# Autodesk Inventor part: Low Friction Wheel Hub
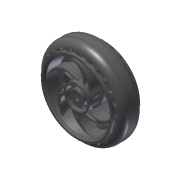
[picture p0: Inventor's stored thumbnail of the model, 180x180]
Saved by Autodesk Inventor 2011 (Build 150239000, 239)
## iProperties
Created: 2010-06
Part Number: Low Friction Wheel Hub
Document SubType Name: Modeling
Designer: kurdi
Density: 1 g/cm^3
Author: kurdi
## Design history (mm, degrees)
sketch "Sketch1"
  geometry: C1 r 4.839 at (0, 0); 1 further point
  constraints: 1 centre point, 1 coincident
  dimensions: "d0" = 9.6774 diameter of C1
extrude "Extrusion1" new body sketch "Sketch1" stored distance "d1" = 19.05; taper "d2" = 0 deg
sketch "Sketch2"
  geometry: C1 r 7.264 at (0, 0); 1 further point
  constraints: 1 centre point, 1 coincident
  dimensions: "d3" = 14.5288 diameter of C1
extrude "Extrusion2" join sketch "Sketch2" stored distance "d4" = 2.0066; taper "d5" = 0 deg
sketch "Sketch3"
  geometry: C1 r 8.585 at (0, 0); C2 r 7.264 at (0, 0) reference; 1 further point
  constraints: 1 centre point, 1 coincident
  dimensions: "d6" = 17.1704 diameter of C1
extrude "Extrusion3" join sketch "Sketch3" stored distance "d7" = 19.05; taper "d8" = 0 deg
sketch "Sketch5"
  geometry: A1 r 22.377 centre (0, 0) between (-12.105, 18.82) and (-12.53, 18.54); A2 r 13.716 centre (-6.985, 6.096) between (6.711, 5.354) and (-12.105, 18.82); A3 r 9.652 centre (-7.874, 9.144) between (1.75, 8.405) and (-4.634, 18.236); A4 r 13.208 centre (-9.068, 5.794) between (-4.634, 18.236) and (-12.53, 18.54); A5 r 12.446 centre (-6.985, 6.096) between (5.449, 6.634) and (2.875, 13.691); A6 r 10.922 centre (-7.874, 9.144) between (2.993, 8.047) and (2.221, 13.313); A7 r 0.381 centre (2.573, 13.458) between (2.875, 13.691) and (2.221, 13.313); A8 r 8.585 centre (0, 0) between (2.993, 8.047) and (5.449, 6.634) reference; A9 r 8.585 centre (0, 0) between (2.993, 8.047) and (1.75, 8.405); A10 r 8.585 centre (0, 0) between (6.711, 5.354) and (5.449, 6.634)
  constraints: 20 point on circle, 9 centre point, 3 concentric, 3 tangent
  dimensions: "d29" = 0.381 radius of A7; "d30" = 22.3774 radius of A1; "d31" = 13.716 radius of A2; "d32" = 9.652 radius of A3; "d33" = 13.208 radius of A4; "d44" = 9.83102 vertical distance of A3.start A3.end; "d45" = 1.27 radial gap between concentric circles of A6 A3; "d46" = 1.27 radial gap between concentric circles of A2 A5; "d47" = 6.096 vertical distance of A1.centre A2.centre; "d48" = 6.985 horizontal distance of A1.centre A2.centre; "d49" = 9.144 vertical distance of A8.centre A3.centre; "d50" = 7.874 horizontal distance of A8.centre A3.centre
extrude "Extrusion4" join sketch "Sketch5" distance "d51" = 6.985; taper "d52" = 0 deg
pattern_circular "Circular Pattern1" dims angle "d54" = 360 deg
sketch "Sketch6"
  geometry: A1 r 4.839 centre (0, 0) between (-2.84, 3.918) and (-4.616, 1.452) reference; A2 r 7.264 centre (0, 0) between (-4.427, 5.759) and (-6.908, 2.246) reference; A3 r 10.922 centre (-11.856, -2.247) between (-2.84, 3.918) and (-4.427, 5.759); A4 r 12.446 centre (-1.787, -9.097) between (-5.01, 2.924) and (-6.908, 2.246); A5 r 1.524 centre (-4.616, 1.452) between (-3.935, 2.816) and (-5.01, 2.924); A6 r 12.446 centre (-1.787, -9.097) between (-8.47, 1.402) and (-13.294, -4.356) reference; A7 r 10.922 centre (-11.856, -2.247) between (-5.472, 6.615) and (-10.419, 8.58) reference; 1 further point
  constraints: 11 point on circle, 4 concentric, 3 centre point, 1 tangent
  dimensions: "d56" = 3.048 diameter of A5
extrude "Extrusion5" join sketch "Sketch6" stored distance "d57" = 13.97; taper "d58" = 0 deg
feature "FaceDraft2" dims angle "d63" = 1 deg
feature "FaceDraft1" dims angle "d62" = 1 deg
feature "FaceDraft6" dims angle "d116" = 1 deg
pattern_circular "Circular Pattern2" dims "d60" = 360 deg
mirror "Mirror1"
sketch "Sketch7"
  geometry: C1 r 22.377 at (0, 0); C2 r 18.466 at (0, 0); A1 r 22.377 centre (0, 0) between (-12.105, 18.82) and (-12.53, 18.54) reference; 1 further point
  constraints: 2 centre point, 2 coincident, 1 concentric
  dimensions: "d64" = 36.9316 diameter of C2
extrude "Extrusion6" join sketch "Sketch7" distance "d65" = 0.762; taper "d66" = 0 deg
feature "FaceDraft3" dims angle "d67" = 1 deg
mirror "Mirror2"
fillet "Fillet2" dims "d69" = 1.778
sketch "Sketch13"
  geometry: L1 (1.612, 0.952)-(1.558, 1.007); L2 (1.558, 1.025)-(1.612, 1.079); L3 (1.612, 1.104)-(1.612, 1.079); L4 (1.558, 1.177)-(1.612, 1.231); L5 (1.612, 1.362)-(1.612, 1.231); L6 (1.232, 1.612)-(1.177, 1.558); L7 (1.159, 1.558)-(1.105, 1.612); L8 (1.079, 1.612)-(1.105, 1.612); L9 (1.232, 1.612)-(1.362, 1.612); L10 (1.612, 0.952)-(1.612, -0.952); L11 (1.558, -1.007)-(1.612, -0.952); L12 (1.612, 1.104)-(1.558, 1.159); L13 (1.079, 1.612)-(1.025, 1.558); L14 (-1.362, 1.612)-(-1.231, 1.612); L15 (-1.177, 1.558)-(-1.231, 1.612); L16 (1.007, 1.558)-(0.952, 1.612); L17 (-0.952, 1.613)-(0.952, 1.612); L18 (-0.952, 1.613)-(-1.007, 1.558); L19 (-1.024, 1.558)-(-1.079, 1.612); L20 (-1.104, 1.613)-(-1.079, 1.612); L21 (-1.104, 1.613)-(-1.159, 1.558); L22 (1.613, -1.079)-(1.558, -1.024); L23 (1.613, -1.079)-(1.612, -1.105); L24 (1.558, -1.159)-(1.612, -1.105); L25 (1.613, -1.231)-(1.558, -1.177); L26 (1.613, -1.231)-(1.612, -1.362); L27 (1.362, -1.612)-(1.231, -1.612); L28 (1.177, -1.558)-(1.231, -1.612); L29 (1.104, -1.613)-(1.079, -1.612); L30 (1.024, -1.558)-(1.079, -1.612); L31 (0.952, -1.613)-(1.007, -1.558); L32 (0.952, -1.613)-(-0.952, -1.612); L33 (1.104, -1.613)-(1.159, -1.558); L34 (-1.007, -1.558)-(-0.952, -1.612); L35 (-1.079, -1.612)-(-1.025, -1.558); L36 (-1.079, -1.612)-(-1.105, -1.612); L37 (-1.159, -1.558)-(-1.105, -1.612); L38 (-1.232, -1.612)-(-1.177, -1.558); L39 (-1.612, -0.952)-(-1.558, -1.007); L40 (-1.558, -1.025)-(-1.612, -1.079); L41 (-1.612, -1.104)-(-1.612, -1.079); L42 (-1.612, -1.104)-(-1.558, -1.159); L43 (-1.558, -1.177)-(-1.612, -1.231); L44 (-1.612, -1.362)-(-1.612, -1.231); L45 (-1.232, -1.612)-(-1.362, -1.612); L46 (-1.612, -0.952)-(-1.612, 0.952); L47 (-1.558, 1.007)-(-1.612, 0.952); L48 (-1.613, 1.079)-(-1.558, 1.024); L49 (-1.613, 1.079)-(-1.612, 1.105); L50 (-1.558, 1.159)-(-1.612, 1.105); L51 (-1.613, 1.231)-(-1.558, 1.177); L52 (-1.613, 1.231)-(-1.612, 1.362); A1 r 0.013 centre (1.567, 1.016) between (1.558, 1.025) and (1.558, 1.007); A2 r 0.013 centre (1.567, 1.168) between (1.558, 1.177) and (1.558, 1.159); A3 r 0.25 centre (1.362, 1.362) between (1.612, 1.362) and (1.362, 1.612); A4 r 0.013 centre (1.168, 1.567) between (1.159, 1.558) and (1.177, 1.558); A5 r 0.012 centre (-1.016, 1.566) between (-1.024, 1.558) and (-1.007, 1.558); A6 r 0.012 centre (-1.168, 1.566) between (-1.177, 1.558) and (-1.159, 1.558); A7 r 0.013 centre (1.016, 1.567) between (1.007, 1.558) and (1.025, 1.558); A8 r 0.012 centre (1.566, -1.016) between (1.558, -1.007) and (1.558, -1.024); A9 r 0.013 centre (1.567, -1.168) between (1.558, -1.159) and (1.558, -1.177); A10 r 0.25 centre (1.362, -1.362) between (1.362, -1.612) and (1.612, -1.362); A11 r 0.012 centre (1.168, -1.566) between (1.177, -1.558) and (1.159, -1.558); A12 r 0.012 centre (1.016, -1.566) between (1.024, -1.558) and (1.007, -1.558); A13 r 0.013 centre (-1.016, -1.567) between (-1.007, -1.558) and (-1.025, -1.558); A14 r 0.013 centre (-1.168, -1.567) between (-1.159, -1.558) and (-1.177, -1.558); A15 r 0.013 centre (-1.567, -1.168) between (-1.558, -1.177) and (-1.558, -1.159); A16 r 0.013 centre (-1.567, -1.016) between (-1.558, -1.025) and (-1.558, -1.007); A17 r 0.25 centre (-1.362, -1.362) between (-1.612, -1.362) and (-1.362, -1.612); A18 r 0.25 centre (-1.362, 1.362) between (-1.362, 1.612) and (-1.612, 1.362); A19 r 0.013 centre (-1.567, 1.168) between (-1.558, 1.159) and (-1.558, 1.177); A20 r 0.012 centre (-1.566, 1.016) between (-1.558, 1.007) and (-1.558, 1.024); 1 further point
  constraints: 104 end point, 40 point on circle, 20 centre point
feature "iFeature1:1" sketch "Sketch13"
sketch "Sketch9"
  geometry: L1 (-4.839, 9.525)-(4.839, 9.525) reference; L2 (50.956, 60.325)-(-50.956, 60.325); A1 r 50.956 centre (0, 60.325) between (-50.956, 60.325) and (50.956, 60.325); A2 r 3.988 centre (0, 9.525) between (-3.988, 9.525) and (3.988, 9.525); 2 further points
  constraints: 5 point on circle, 2 centre point, 2 end point, 2 midpoint, 2 point on line, 1 coincident, 1 parallel, 1 vertical alignment
  dimensions: "d73" = 50.8 distance from line of L1 A1.centre; "d75" = 7.9756 diameter of A2
revolve "Revolution1" sketch "Sketch9" stored, may be unused: angle "d76" = 90 deg
mirror "Mirror3"
sketch "Sketch10"
  geometry: L1 (19.863, 0)-(21.463, 8.255); L2 (21.463, 8.255)-(22.733, 9.525); L3 (22.733, 9.525)-(23.812, 9.525); L4 (23.812, 9.525)-(23.812, 6.985); L5 (28.791, 0)-(19.863, 0); L6 (-8.585, 9.525)-(8.585, 9.525) reference; L7 (23.812, 6.985)-(24.117, 6.985); L8 (28.791, 2.311)-(28.791, 0); L9 (0, -13.335)-(0, 13.335) reference; L10 (19.863, 0)-(21.463, -8.255); L11 (21.463, -8.255)-(22.733, -9.525); L12 (22.733, -9.525)-(23.813, -9.525); L13 (23.813, -9.525)-(23.812, -6.985); L14 (23.812, -6.985)-(24.117, -6.985); L15 (28.791, -2.311)-(28.791, 0); A1 r 4.674 centre (24.117, 2.311) between (28.791, 2.311) and (24.117, 6.985); A2 r 4.674 centre (24.117, -2.311) between (24.117, -6.985) and (28.791, -2.311); 1 further point
  constraints: 26 end point, 7 symmetric about line, 4 point on circle, 3 perpendicular, 2 centre point, 1 collinear, 1 horizontal, 1 horizontal alignment, 1 parallel, 1 point on line, 1 tangent, 1 other
  dimensions: "d77" = 19.8628 distance of L1.start point (0, 0); "d78" = 21.463 horizontal distance of L1.end point (0, 0); "d79" = 23.8125 distance from line of L4 point (0, 0); "d80" = 1.27 horizontal distance of L1.end L2.end; "d81" = 1.27 horizontal distance of L1.end L2.end; "d83" = 4.6736 radius of A1; "d84" = 0.3048 distance of L4.end L7.end; "d85" = 2.3114 distance of L8.start L5.start
workaxis "Work Axis1"
sketch "Sketch12"
  geometry: L1 (-10.806, 21.447)-(-12.671, 21.947); L2 (-12.671, 21.947)-(-13.171, 20.082); L3 (-10.754, 21.643)-(-12.618, 22.143); L4 (-12.867, 21.999)-(-13.367, 20.135); L5 (0, 0)-(-12.7, 21.997); L6 (0, 0)-(0, 8.585); A1 r 24.016 centre (0, 0) between (-10.806, 21.447) and (-13.171, 20.082); A2 r 23.812 centre (0, 0) between (-10.715, 21.266) and (-13.059, 19.912); A3 r 0.203 centre (-10.806, 21.447) between (-10.715, 21.266) and (-10.754, 21.643); A4 r 0.203 centre (-13.171, 20.082) between (-13.367, 20.135) and (-13.059, 19.912); A5 r 0.203 centre (-12.671, 21.947) between (-12.618, 22.143) and (-12.867, 21.999); A6 r 18.466 centre (0, 0) between (-4.246, 17.971) and (-12.334, 13.742) reference; 3 further points
  constraints: 12 end point, 11 point on circle, 6 tangent, 5 centre point, 2 coincident, 2 perpendicular, 1 concentric, 1 equal radius, 1 point on line, 1 vertical alignment, 2 other
  dimensions: "d90" = 1.9304 distance of L1.start L1.end; "d91" = 1.9304 distance of L1.end L2.end; "d92" = 0.2032 distance between parallel lines of L2 L4; "d93" = 0.2032 radius of A3; "d94" = 0.2032 radius of A5; "d98" = 23.8125 radius of A2; "d101" = 0.2032 radial gap between concentric circles of A1 A2; "d102" = 25.4 distance of L5.start L5.end; "d118" = 30 deg angle of L5 L6
extrude "Extrusion9" join sketch "Sketch12" stored distance "d96" = 16.002; taper "d97" = 0 deg
fillet "Fillet3" dims "d103" = 0.2032
revolve "Revolution2" stored, may be unused: angle "d86" = 90 deg
sketch "Sketch11"
  geometry: A1 r 12.446 centre (-8.772, -3.001) between (-3.021, 8.036) and (-10.419, 9.335) reference; A2 r 10.922 centre (-11.856, -2.247) between (-5.472, 6.615) and (-10.419, 8.58) reference; A3 r 0.381 centre (-10.369, 8.958) between (-10.419, 9.335) and (-10.419, 8.58) reference; A4 r 10.922 centre (-7.874, 9.144) between (2.993, 8.047) and (2.221, 13.313) reference; A5 r 12.446 centre (-6.985, 6.096) between (5.449, 6.634) and (2.875, 13.691) reference; A6 r 0.381 centre (2.573, 13.458) between (2.875, 13.691) and (2.221, 13.313) reference; A7 r 0.381 centre (12.942, 4.501) between (13.294, 4.356) and (12.64, 4.733) reference; A8 r 10.922 centre (3.982, 11.391) between (8.465, 1.432) and (12.64, 4.733) reference; A9 r 12.446 centre (1.787, 9.097) between (8.47, -1.402) and (13.294, 4.356) reference; A10 r 0.381 centre (10.369, -8.958) between (10.419, -9.335) and (10.419, -8.58) reference; A11 r 10.922 centre (11.856, 2.247) between (5.472, -6.615) and (10.419, -8.58) reference; A12 r 12.446 centre (8.772, 3.001) between (3.021, -8.036) and (10.419, -9.335) reference; A13 r 10.922 centre (7.874, -9.144) between (-2.993, -8.047) and (-2.221, -13.313) reference; A14 r 0.381 centre (-2.573, -13.458) between (-2.875, -13.691) and (-2.221, -13.313) reference; A15 r 12.446 centre (6.985, -6.096) between (-5.449, -6.634) and (-2.875, -13.691) reference; A16 r 10.922 centre (-3.982, -11.391) between (-8.465, -1.432) and (-12.64, -4.733) reference; A17 r 0.381 centre (-12.942, -4.501) between (-13.294, -4.356) and (-12.64, -4.733) reference; A18 r 12.446 centre (-1.787, -9.097) between (-8.47, 1.402) and (-13.294, -4.356) reference; 2 further points
  constraints: 1 other
extrude "Extrusion8" join sketch "Sketch11" stored distance "d87" = 2.0066; taper "d88" = 0 deg
feature "FaceDraft4" dims angle "d112" = 1 deg
feature "FaceDraft5" dims angle "d113" = 1 deg
fillet "Fillet4" dims "d110" = 0.381
fillet "Fillet6" dims "d114" = 0.3048
fillet "Fillet7" dims "d115" = 0.254
fillet "Fillet8" dims "d117" = 0.254
sketch "Sketch14"
  geometry: L1 (0, 0)-(0, 23.559); L2 (0, 0)-(-11.779, 20.402); L3 (-11.779, 18.091)-(-11.779, 20.402); L4 (-9.778, 19.247)-(-11.779, 20.402); A1 r 23.559 centre (0, 0) between (-11.779, 20.402) and (0, 23.559) reference; A2 r 21.866 centre (0.139, -0.241) between (-9.778, 19.247) and (-11.779, 18.091); 1 further point
  constraints: 8 end point, 4 point on circle, 1 centre point, 1 point on line, 1 vertical
  dimensions: "d119" = 30 deg angle of L1 L2; "d133" = 30 deg angle of L2 L3; "d134" = 60 deg angle of L4 L3; "d135" = 2.3114 distance of L3.start L2.end; "d136" = 2.3114 distance of L4.start L2.end; "d137" = 21.86559 radius of A2
extrude "Extrusion10" join sketch "Sketch14" distance "d122" = 9.906; taper "d123" = 0 deg
sketch "Sketch15"
  geometry: L1 (-23.559, 9.525)-(23.559, 9.525) reference; L2 (21.463, 8.255)-(22.659, 9.451) reference; L3 (10.873, 9.451)-(11.779, 9.451) reference; L4 (11.779, 9.525)-(11.055, 9.525) reference; L5 (22.838, 9.906)-(23.559, 9.906); L6 (21.273, 8.603)-(22.389, 9.72); L7 (23.559, 9.906)-(23.559, 10.16); L8 (23.559, 10.16)-(21.273, 10.16); L9 (21.273, 10.16)-(21.273, 8.603); L10 (0, -13.462)-(0, 14.097) reference; A1 r 0.635 centre (22.838, 9.271) between (22.838, 9.906) and (22.389, 9.72); 2 further points
  constraints: 10 end point, 3 parallel, 2 perpendicular, 2 point on circle, 2 tangent, 1 centre point, 1 point on line, 1 vertical alignment, 1 other
  dimensions: "d124" = 0.381 distance between parallel lines of L5 L1; "d125" = 0.381 distance between parallel lines of L2 L6; "d126" = 0.635 radius of A1; "d127" = 0.254 distance of L5.end L7.end; "d128" = 2.286 distance of L7.end L8.end
revolve "Revolution3" sketch "Sketch15" stored, may be unused: angle "d129" = 90 deg
body "Solid1"
pattern_circular "Circular Pattern4" dims angle "d108" = 360 deg
node "Projected Loop1"
other parameters: "d17" = 1.27
